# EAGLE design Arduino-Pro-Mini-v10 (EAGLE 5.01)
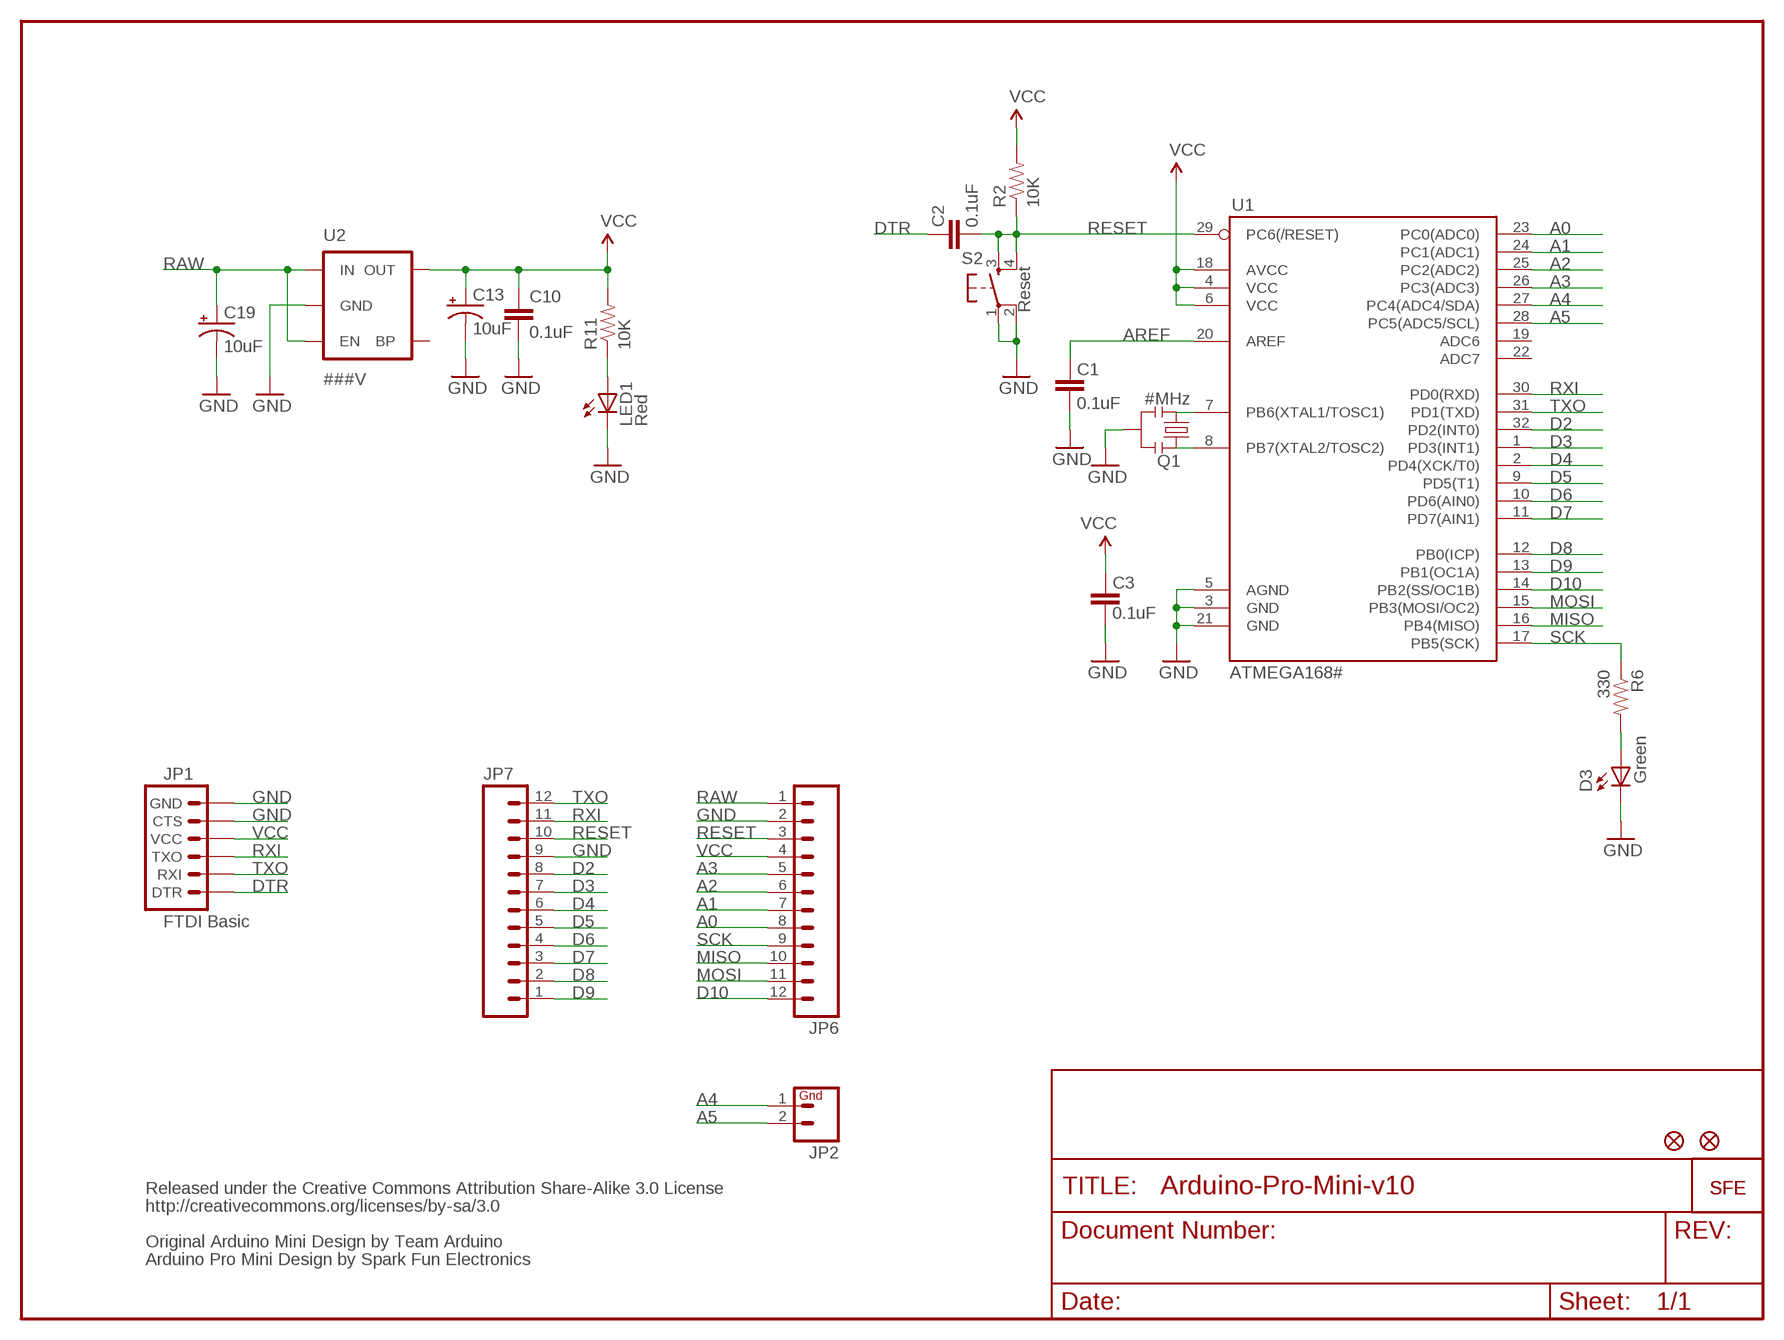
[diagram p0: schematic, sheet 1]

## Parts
C1  0.1uF  CAP0402  [C0402]
C2  0.1uF  CAP0402  [C0402]
C3  0.1uF  CAP0402  [C0402]
C10  0.1uF  CAP0402  [C0402]
C13  10uF  CAP_POL1206  [EIA3216]
C19  10uF  CAP_POL1206  [EIA3216]
D3  Green  LED0603  [LED-0603]
JP1  FTDI Basic  ARDUINO_SERIAL_PROGRAMPTH  [1X06]
JP2  M02PTH  [1X02]
JP6  M12PTH  [1X12]
JP7  M12PTH  [1X12]
LED1  Red  LED0603  [LED-0603]
Q1  #MHz  RESONATORSMD  [RESONATOR-SMD]
R2  10K  RESISTOR0402  [C0402]
R6  330  RESISTOR0402  [C0402]
R11  10K  RESISTOR0402  [C0402]
S2  Reset  TAC_SWITCHSND  [TACTILE_SWITCH_SMD]
U1  ATMEGA168#  ATMEGA168  [TQFP32-08]
U2  ###V  V_REG_LDOSMD  [SOT23-5]
U$1  LOGO-SFESK  [SFE-LOGO-FLAME]
U$2  FIDUCIAL1X2  [FIDUCIAL-1X2]
U$4  FIDUCIAL1X2  [FIDUCIAL-1X2]
U$11  LOGO-SFENEW  [SFE-NEW-WEBLOGO]

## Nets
A0: JP6.8 U1.23(PC0(ADC0))
A1: JP6.7 U1.24(PC1(ADC1))
A2: JP6.6 U1.25(PC2(ADC2))
A3: JP6.5 U1.26(PC3(ADC3))
A4: JP2.1 U1.27(PC4(ADC4/SDA))
A5: JP2.2 U1.28(PC5(ADC5/SCL))
AREF: C1.2 U1.20(AREF)
D2: JP7.8 U1.32(PD2(INT0))
D3: JP7.7 U1.1(PD3(INT1))
D4: JP7.6 U1.2(PD4(XCK/T0))
D5: JP7.5 U1.9(PD5(T1))
D6: JP7.4 U1.10(PD6(AIN0))
D7: JP7.3 U1.11(PD7(AIN1))
D8: JP7.2 U1.12(PB0(ICP))
D9: JP7.1 U1.13(PB1(OC1A))
D10: JP6.12 U1.14(PB2(SS/OC1B))
DTR: C2.2 JP1.1(DTR)
GND [vcc]: C1.1 C3.1 C10.2 C13.C(-) C19.C(-) D3.C JP1.5(CTS) JP1.6(GND) JP6.2 JP7.9 LED1.C Q1.2 S2.1 S2.2 U1.3(GND) U1.5(AGND) U1.21(GND) U2.2(GND)
MISO: JP6.10 U1.16(PB4(MISO))
MOSI: JP6.11 U1.15(PB3(MOSI/OC2))
N$1: Q1.1 U1.8(PB7(XTAL2/TOSC2))
N$2: Q1.3 U1.7(PB6(XTAL1/TOSC1))
N$7: D3.A R6.2
N$38: LED1.A R11.1
RAW [vcc]: C19.A(+) JP6.1 U2.1(IN) U2.3(EN)
RESET: C2.1 JP6.3 JP7.10 R2.1 S2.3 S2.4 U1.29(PC6(/RESET))
RXI: JP1.3(TXO) JP7.11 U1.30(PD0(RXD))
SCK: JP6.9 R6.1 U1.17(PB5(SCK))
TXO: JP1.2(RXI) JP7.12 U1.31(PD1(TXD))
VCC: C3.2 C10.1 C13.A(+) JP1.4(VCC) JP6.4 R2.2 R11.2 U1.4(VCC) U1.6(VCC) U1.18(AVCC) U2.5(OUT)
Unconnected: U1.19(ADC6) U1.22(ADC7) U2.4(BP)

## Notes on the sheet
- Released under the Creative Commons Attribution Share-Alike 3.0 License
- http://creativecommons.org/licenses/by-sa/3.0
- Original Arduino Mini Design by Team Arduino
- Arduino Pro Mini Design by Spark Fun Electronics

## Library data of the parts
C1-C3 C10 = SparkFun:CAP: Capacitor
C13 C19 = SparkFun:CAP_POL: Capacitor Polarized
D3 LED1 = SparkFun:LED: LEDs
JP1 = SparkFun:ARDUINO_SERIAL_PROGRAM
JP2 = SparkFun:M02: Header 2
JP6 JP7 = SparkFun:M12: Header 12 Standard 12-pin 0.1" header. Use with straight break away headers (SKU : PRT-00116), right angle break away headers (PRT-00553), swiss pins (PRT-00743), machine pins (PRT-00117), and female headers (PRT-00115).
Q1 = SparkFun:RESONATOR: Resonator Small SMD resonator. This is the itty bitty 10/20MHz resonators with built in caps. CSTCE10M0G55 and CSTCE20M0V53. Footprint has been reviewed closely but hasn't been tested yet.
R2 R6 R11 = SparkFun:RESISTOR: Resistor
S2 = SparkFun:TAC_SWITCH: Momentary Switch Button commonly used for reset or general input. Spark Fun Electronics SKU : COM-00097
U1 = SparkFun:ATMEGA168
U2 = SparkFun:V_REG_LDO: Voltage Regulator LDO Standard 150mA LDO voltage regulator in SOT-23 layout. Micrel part MIC5205. BP (by-pass) pin is used to lower output noise with 470pF cap.
U$1 U$11 = SparkFun:LOGO-SFE: Spark Fun Electronics PCB Logo
U$2 U$4 = SparkFun:FIDUCIAL: Fiducial Alignment Points

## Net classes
0 default: width 0.203 mm
1 vcc: width 0.254 mm

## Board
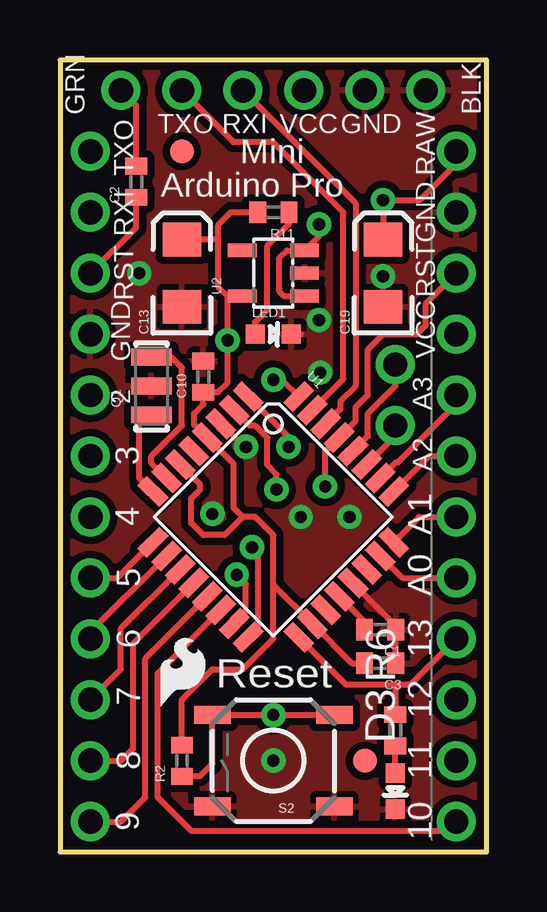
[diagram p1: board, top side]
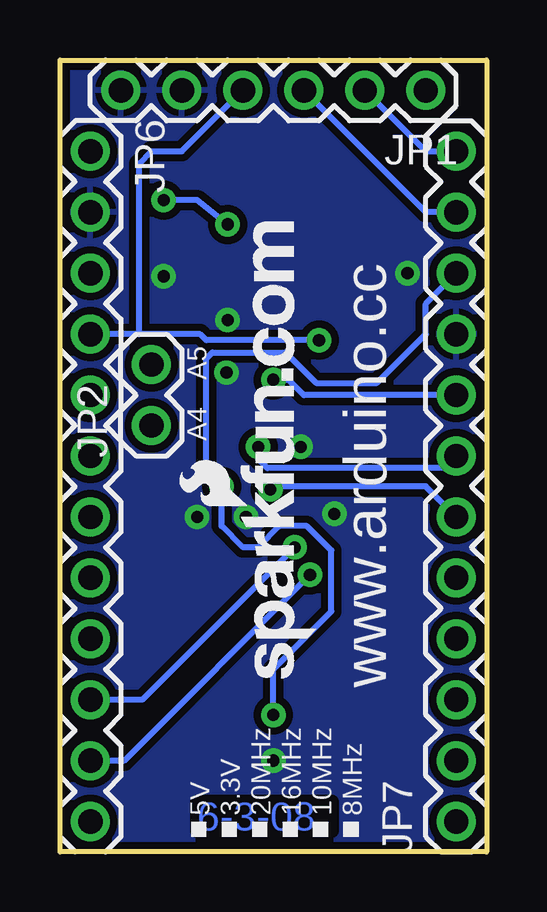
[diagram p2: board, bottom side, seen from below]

Size 17.78 x 33.02 mm. Coordinates in mm from the lower left corner, seen from the top.
Outline: 0,33.02 0,0 17.78,0 17.78,33.02 0,33.02
Copper layers (1*16): Top 0.035mm / dielectric 1.5mm / Bottom 0.035mm
Design rules "SparkFun *": minimum track width 8mil, minimum drill 20mil, track to track 8mil, track to pad 8mil, pad to pad 8mil, via to via 8mil, smd to smd 8mil, copper to edge 10mil, drill to drill 8mil, minimum pad ring 12mil, minimum via ring 10mil, stop-mask expansion 4mil, vias tented up to drill 20mil, thermal gap 10mil

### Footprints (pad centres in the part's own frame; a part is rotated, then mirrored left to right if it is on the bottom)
C0402 = smd 0.7 x 0.9: 1 -0.65,0; 2 0.65,0
EIA3216 = smd 1.4 x 1.6: A 1.4,0; C -1.4,0
LED-0603 = smd 0.8 x 0.8: A 0,-0.75; C 0,0.75
1X06 = drill 1.016 round: 1 0,0; 2 2.54,0; 3 5.08,0; 4 7.62,0; 5 10.16,0; 6 12.7,0
1X02 = drill 1.016 round: 1 0,0; 2 2.54,0
1X12 = drill 1.016 round: 1 0,0; 2 2.54,0; 3 5.08,0; 4 7.62,0; 5 10.16,0; 6 12.7,0; 7 15.24,0; 8 17.78,0; 9 20.32,0; 10 22.86,0; 11 25.4,0; 12 27.94,0
RESONATOR-SMD = smd 0.7 x 1.7: 1 -1.2,0; 2 0,0; 3 1.2,0
TACTILE_SWITCH_SMD = smd 1.524 x 0.762: 1 -2.54,1.905; 2 2.54,1.905; 3 -2.54,-1.905; 4 2.54,-1.905
TQFP32-08 = smd 1.27 x 0.559: 1 -4.293,2.8; 2 -4.293,2; 3 -4.293,1.2; 4 -4.293,0.4; 5 -4.293,-0.4; 6 -4.293,-1.2; 7 -4.293,-2; 8 -4.293,-2.8; 17 4.293,-2.8; 18 4.293,-2; 19 4.293,-1.2; 20 4.293,-0.4; 21 4.293,0.4; 22 4.293,1.2; 23 4.293,2; 24 4.293,2.8 | smd 0.559 x 1.27: 9 -2.8,-4.293; 10 -2,-4.293; 11 -1.2,-4.293; 12 -0.4,-4.293; 13 0.4,-4.293; 14 1.2,-4.293; 15 2,-4.293; 16 2.8,-4.293; 25 2.8,4.293; 26 2,4.293; 27 1.2,4.293; 28 0.4,4.293; 29 -0.4,4.293; 30 -1.2,4.293; 31 -2,4.293; 32 -2.8,4.293
SOT23-5 = smd 0.55 x 1.2: 1 -0.95,-1.3; 2 0,-1.3; 3 0.95,-1.3; 4 0.95,1.3; 5 -0.95,1.3
FIDUCIAL-1X2 = smd 1 x 1: 1 0,0

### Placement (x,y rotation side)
C1  13.34,9.27 180 top
C2  3.17,27.94 90 top
C3  13.34,7.87 180 top
C10  5.97,19.81 90 top
C13  5.08,24.13 90 top
C19  13.46,24.13 90 top
D3  13.97,2.54 180 top
JP1  2.54,31.75 180 bottom
JP2  13.97,17.78 90 bottom
JP6  16.51,29.21 270 bottom
JP7  1.27,1.27 90 bottom
LED1  8.89,21.59 270 top
Q1  3.81,19.43 90 top
R2  5.08,3.81 90 top
R6  13.97,5.08 270 top
R11  8.89,26.67 180 top
S2  8.89,3.81 180 top
U1  8.89,13.97 315 top
U2  8.89,24.13 90 top
U$1  4.19,6.1 0 top
U$2  12.7,3.81 0 top
U$4  5.08,29.21 0 top
U$11  7.11,7.24 90 bottom

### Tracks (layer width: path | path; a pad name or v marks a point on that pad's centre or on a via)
A0
  Top 0.254: U1.23 14.26,11.43 JP6.8
A1
  Top 0.254: U1.24 14.96,13.97 JP6.7
A2
  Top 0.254: U1.25 15.39,16.51 JP6.6
A3
  Top 0.254: 16.51,18.8 16.51,18.76 | U1.26 14,16.26 14.1,16.26 16.51,18.67 16.51,18.8 | 16.51,18.8 JP6.5
A4
  Top 0.254: U1.27 13.97,17.35 JP2.1
A5
  Top 0.254: U1.28 12.83,17.34 12.83,18.29 13.97,19.43 JP2.2
AREF
  Top 0.254: C1.2 12.7,9.59 U1.20
D2  (via drill 0.51)
  Top 0.254: U1.32 9.25,19.68 v8.89,19.68
  Bottom 0.254: JP7.8 7.62,19.05 8.26,19.68 v8.89,19.68
D3  (via drill 0.51)
  Top 0.254: U1.1 9.53,17.3 v9.53,16.89
  Bottom 0.254: v9.53,16.89 9.53,16.38 9.14,16 1.78,16 JP7.7
D4  (via drill 0.51)
  Top 0.254: v9.02,15.11 9.02,15.75 8.64,16.13 8.64,17.27 8.13,17.78 7.91,17.78 U1.2
  Bottom 0.254: JP7.6 2.54,15.24 8.89,15.24 v9.02,15.11
D5
  Top 0.254: U1.9 2.39,11.43 JP7.5
D6
  Top 0.254: U1.10 1.27,9.18 JP7.4
D7
  Top 0.254: U1.11 2.54,9.32 2.54,7.62 JP7.3
D8
  Top 0.254: U1.12 3.05,8.69 3.05,4.32 2.54,3.81 JP7.2
D9
  Top 0.254: JP7.1 2.54,1.27 3.56,2.29 3.56,8.07 U1.13
D10
  Top 0.254: JP6.12 16.13,0.89 5.46,0.89 4.06,2.29 4.06,7.45 U1.14
DTR
  Top 0.254: C2.2 3.17,31.11 JP1.1
GND  (via drill 0.51)
  Top 0.254: C3.1 13.97,7.87 13.97,9.26 C1.1 13.97,9.27 13.97,9.46 U1.21 | LED1.C 10.03,21.59 | U1.3 7.62,16.94 v7.75,16.89
  other vias: 12.06,13.97 10.03,13.97 8.89,3.81 3.3,24.13 10.85,19.99 10.79,22.17 6.35,14.1 13.46,24
  pour Top (isolate 0.305): 0,33.02 17.78,33.02 17.78,0 0,0
  pour Bottom (isolate 0.305): 0,33.02 17.78,33.02 17.78,0 0,0
MISO  (via drill 0.51)
  Top 0.254: U1.16 8.26,9.38 8.26,12.45 v8,12.7
  Bottom 0.254: v8,12.7 14.35,6.35 JP6.10
MOSI  (via drill 0.51)
  Top 0.254: U1.15 7.75,10 7.75,11.18 v7.37,11.56
  Bottom 0.254: JP6.11 15.11,3.81 v7.37,11.56
N$1
  Top 0.254: Q1.1 3.61,18.16 3.3,18.16 3.3,15.6 U1.8
N$2
  Top 0.254: U1.7 3.81,16.22 3.81,16.51 5.08,17.78 5.08,20.19 4.64,20.63 Q1.3
N$7
  Top 0.254: D3.A R6.2
N$38
  Top 0.254: R11.1 9.54,26.18 8.64,25.27 8.64,22.61 8.13,22.1 8.13,21.59 LED1.A
RAW  (via drill 0.51)
  Top 0.254: JP6.1 16.51,28.7 14.98,27.18 14.99,27.18 v13.46,27.18 C19.A | v10.79,26.16 10.79,25.68 U2.3 9.46,25.08 9.14,24.77 9.14,23.5 9.14,23.37 9.33,23.18 U2.1
  Bottom 0.254: v10.79,26.16 12.06,27.18 v13.46,27.18
RESET  (via drill 0.51)
  Top 0.254: R2.1 5.09,3.17 5.84,3.17 6.35,3.68 S2.4 v8.89,5.71 S2.3 | JP6.3 15.24,22.86 15.24,21.97 14.86,21.59 13.46,21.59 12.83,20.95 12.83,19.05 12.32,18.54 12.32,17.96 U1.29 11.05,16.7 v11.05,15.24 | C2.1 3.17,26.04 JP7.10
  Bottom 0.254: v8.89,5.71 8.89,7.62 6.48,10.03 6.48,12.57 7.49,13.59 8.64,13.59 9.53,12.7 10.16,12.7 11.05,13.59 v11.05,15.24 11.68,15.88 11.68,20.57 11.43,20.83 8.38,20.83 7.11,19.56 4.57,19.56 2.54,21.59 2.54,22.86 JP7.10
RXI
  Top 0.254: U1.30 11.68,18.46 11.68,18.8 12.32,19.43 12.32,27.05 JP1.3
  Bottom 0.254: JP7.11 2.54,26.67 JP1.3
SCK
  Top 0.254: 13.97,6.99 11.94,6.99 11.91,6.99 U1.17 | 13.97,6.99 14.61,6.99 JP6.9 | 13.97,6.99 R6.1
TXO
  Top 0.254: U1.31 11.81,19.72 11.81,26.67 8.89,29.59 7.24,29.59 JP1.2
  Bottom 0.254: JP7.12 2.54,29.21 JP1.2
VCC  (via drill 0.51)
  Top 0.254: C13.A 6.6,25.53 | R11.2 7.11,26.67 6.6,26.16 6.6,25.53 | 8.94,11.1 U1.18 12.16,7.87 C3.2 | 8.94,11.1 8.89,11.14 | R2.2 5.08,6.35 6.35,7.62 7.62,7.62 8.89,8.89 8.89,11.05 | 8.89,11.05 8.94,11.1 | 7.62,13.97 7.24,14.35 7.24,16.19 U1.4 6.11,17.29 | 7.62,13.97 8.13,13.97 8.89,13.21 8.89,11.05 | 8.89,11.05 | 6.11,17.29 6.1,17.27 | 6.99,23.18 U2.5 | 6.11,17.29 5.59,17.81 5.59,18.29 5.97,18.67 C10.1 5.95,19.16 5.97,19.18 6.6,19.18 6.99,19.56 v6.99,21.34 6.99,23.18 | 6.99,23.18 6.6,23.56 6.6,25.53 | U1.6 5.84,15.32 5.84,15.11 5.46,14.73 5.46,13.72 5.97,13.21 6.86,13.21 7.62,13.97
  Top 0.305: C10.1 5.84,19.18
  Bottom 0.254: 14.48,21.59 JP6.4 | 14.48,21.59 14.48,28.7 13.97,29.21 12.7,29.21 JP1.4 | 14.48,21.59 11.94,21.59 11.68,21.34 v6.99,21.34

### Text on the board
Bottom: 6-3-08
tPlace: GRN | BLK | TXO | RXI | VCC | GND | Mini | TXO | RAW | Arduino Pro | RXI | GND | RST | RST | VCC | GND | 2 | A3 | 3 | A2 | 4 | A1 | 5 | A0 | 6 | 13 | Reset | 7 | 12 | 8 | 11 | 9 | 10 | Released under the Creative Commons Attribution Share-Alike 3.0 License | http://creativecommons.org/licenses/by-sa/3.0
bPlace: A5 | A4 | www.arduino.cc | 8MHz | 10MHz | 16MHz | 20MHz | 3.3V | 5V
tValues: Tent Vias! | Arduino Wee v1.3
